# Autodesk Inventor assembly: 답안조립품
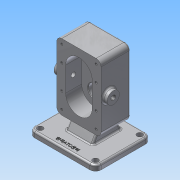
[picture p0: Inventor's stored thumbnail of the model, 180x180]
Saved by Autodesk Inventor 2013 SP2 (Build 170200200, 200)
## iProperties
Created: 2026-10
Part Number: 답안조립품
Document SubType Name: Assembly
Designer: a
Author: a
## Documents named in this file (2)
- C:\Users\a\Desktop\761003V1007\답안조립품.iam
- C:\Users\a\Desktop\761003V1007\본체.ipt
